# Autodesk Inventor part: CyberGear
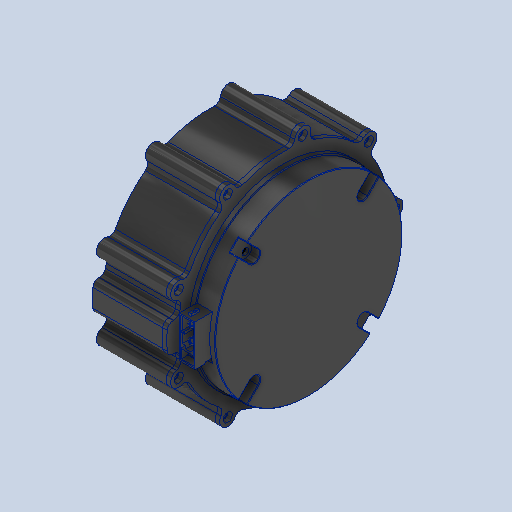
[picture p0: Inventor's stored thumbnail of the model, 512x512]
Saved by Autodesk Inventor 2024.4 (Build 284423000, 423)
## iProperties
Created: 2026-01
Part Number: CyberGear
Material: Generic
Document SubType Name: Modeling
Designer: AdminForWorker
Density: 1 g/cm^3
Appearance: Default
Title: CyberGear (2)
Author: AdminForWorker
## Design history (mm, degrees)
feature "Body1"
feature "Body2"
feature "Body3"
feature "Body4"
feature "Body5"
feature "Body6"
feature "Body7"
feature "Body8"
body "Solid1"
body "Solid2"
body "Solid3"
body "Solid4"
body "Solid5"
body "Solid6"
body "Solid7"
body "Solid8"
